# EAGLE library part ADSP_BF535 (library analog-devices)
Blackfin® Embedded Processor ADSP 535 Auto generated by make-symbol-device-package-bsdl.ulp Rev. 11 Source: ADSP_21535.bsdl http://www.analog.com/UploadedFiles/Data_Sheets/744511807ADSP_BF535_a.pdf
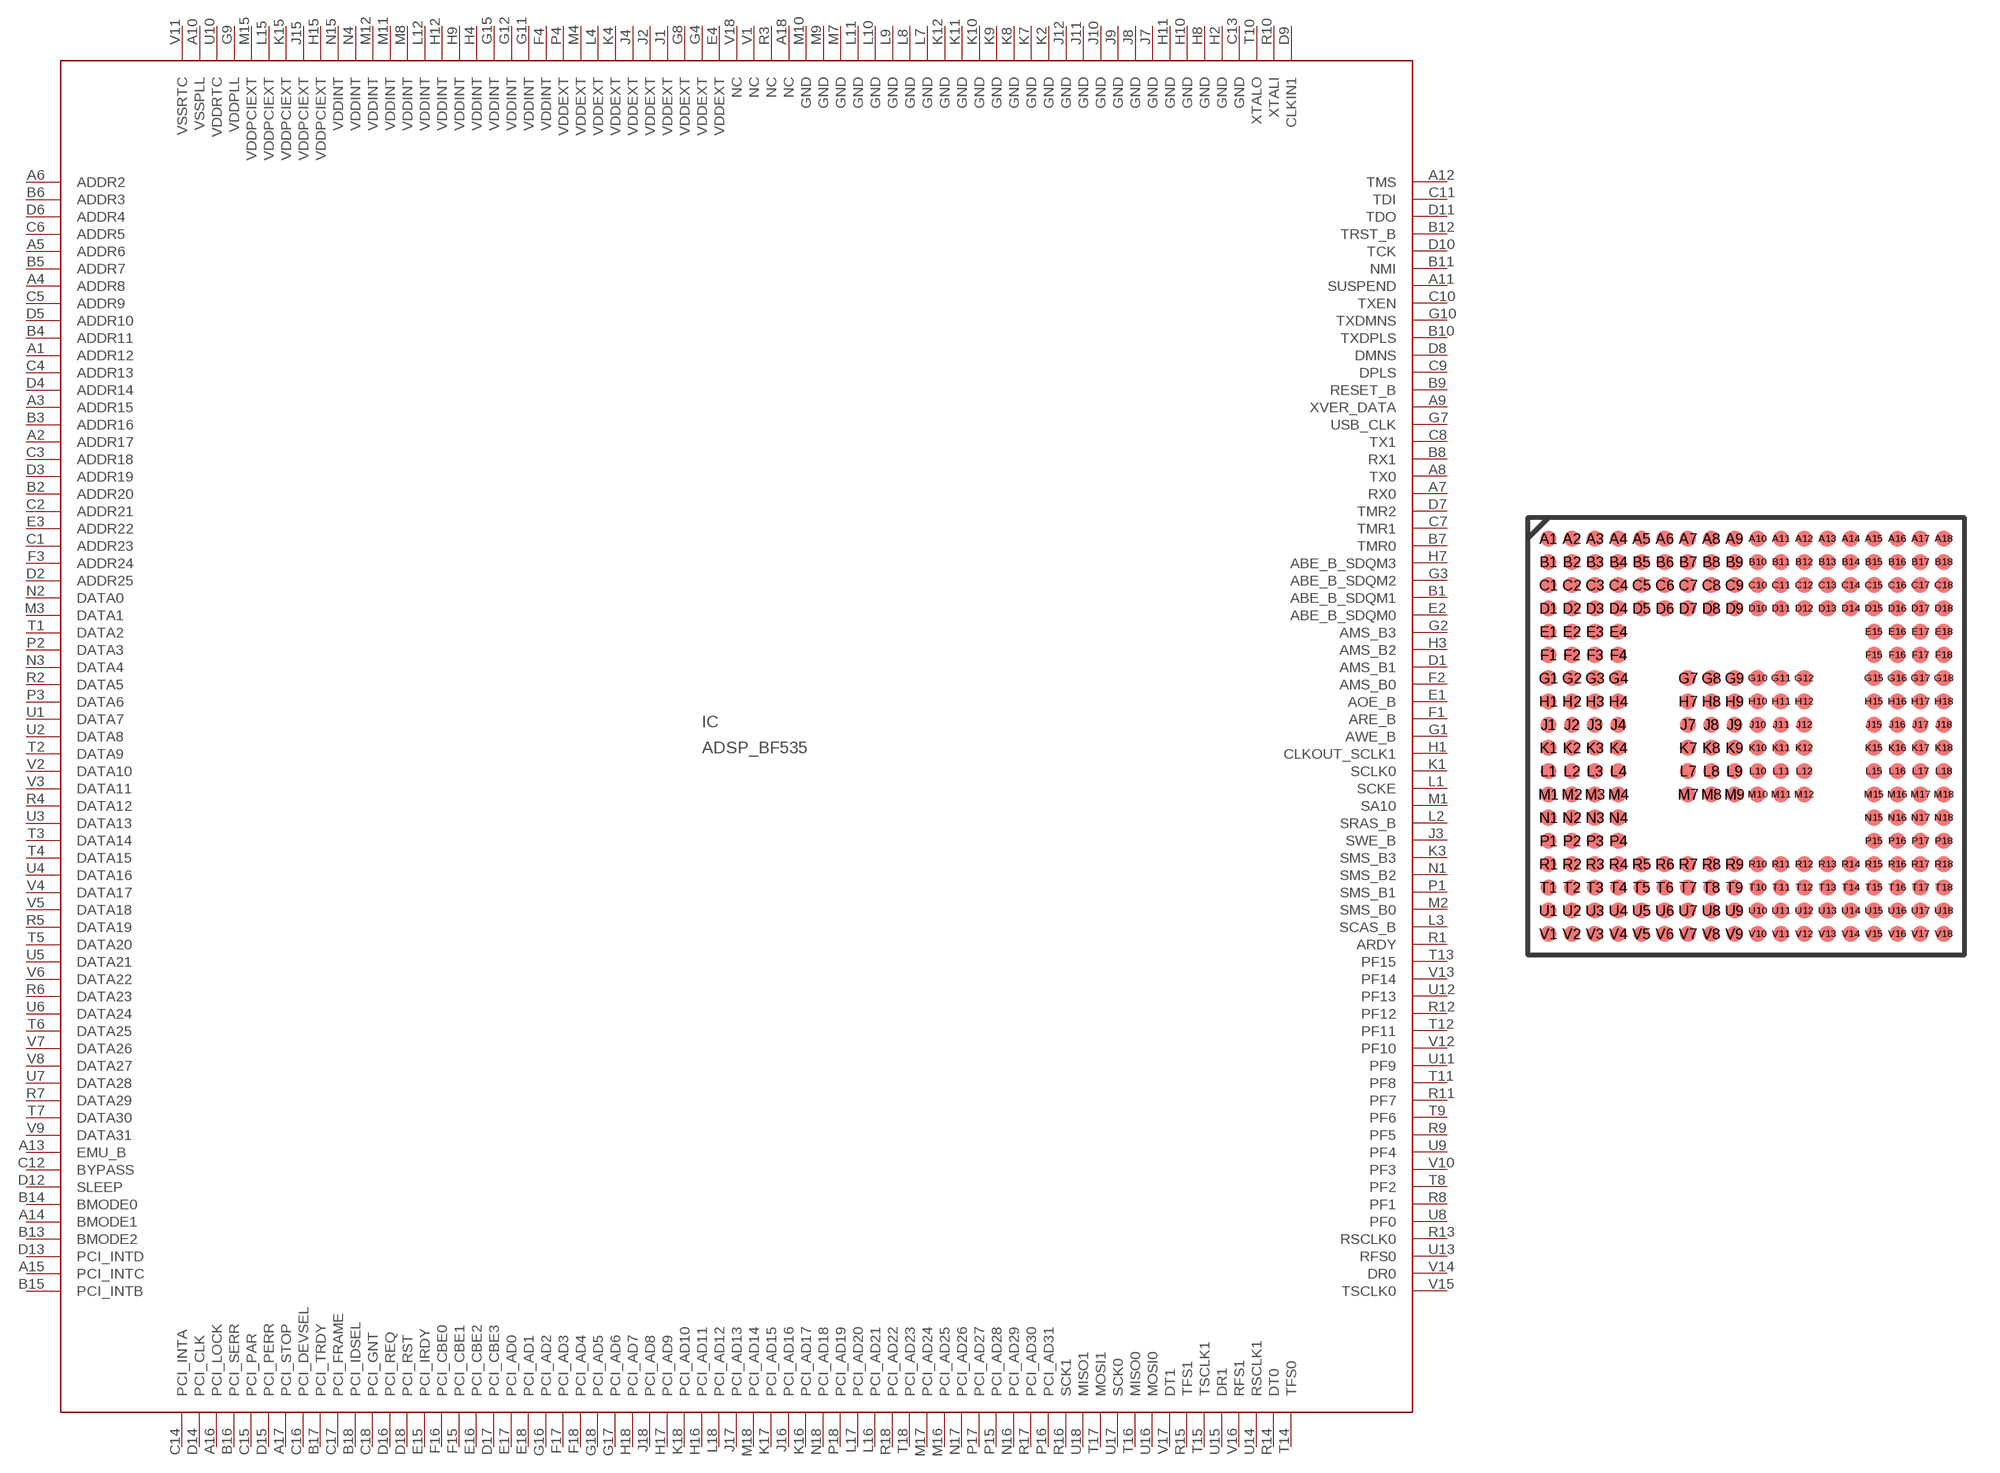
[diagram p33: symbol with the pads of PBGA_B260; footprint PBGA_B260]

Designator prefix IC

## ADSP_BF535 (OC_FARNELL: 1439074; OC_NEWARK: unknown)  [PBGA_B260]
A1  ADDR12  out
A2  ADDR17  out
A3  ADDR15  out
A4  ADDR8  out
A5  ADDR6  out
A6  ADDR2  out
A7  RX0  in
A8  TX0  out
A9  XVER_DATA  in
A10  VSSPLL  pwr
A11  SUSPEND  out
A12  TMS  in
A13  EMU_B  out
A14  BMODE1  in
A15  PCI_INTC  in
A16  PCI_LOCK  in
A17  PCI_STOP
A18  NC  pwr
B1  ABE_B_SDQM1  out
B2  ADDR20  out
B3  ADDR16  out
B4  ADDR11  out
B5  ADDR7  out
B6  ADDR3  out
B7  TMR0
B8  RX1  in
B9  RESET_B  in
B10  TXDPLS  out
B11  NMI  in
B12  TRST_B  in
B13  BMODE2  in
B14  BMODE0  in
B15  PCI_INTB  in
B16  PCI_SERR
B17  PCI_TRDY
B18  PCI_IDSEL  in
C1  ADDR23  out
C2  ADDR21  out
C3  ADDR18  out
C4  ADDR13  out
C5  ADDR9  out
C6  ADDR5  out
C7  TMR1
C8  TX1  out
C9  DPLS  in
C10  TXEN  out
C11  TDI  in
C12  BYPASS  in
C13  GND  pwr
C14  PCI_INTA
C15  PCI_PAR
C16  PCI_DEVSEL
C17  PCI_FRAME
C18  PCI_GNT  in
D1  AMS_B1  out
D2  ADDR25  out
D3  ADDR19  out
D4  ADDR14  out
D5  ADDR10  out
D6  ADDR4  out
D7  TMR2
D8  DMNS  in
D9  CLKIN1  pwr
D10  TCK  in
D11  TDO  out
D12  SLEEP  out
D13  PCI_INTD  in
D14  PCI_CLK  in
D15  PCI_PERR
D16  PCI_REQ  out
D17  PCI_CBE3
D18  PCI_RST
E1  AOE_B  out
E2  ABE_B_SDQM0  out
E3  ADDR22  out
E4  VDDEXT  pwr
E15  PCI_IRDY
E16  PCI_CBE2
E17  PCI_AD0
E18  PCI_AD1
F1  ARE_B  out
F2  AMS_B0  out
F3  ADDR24  out
F4  VDDINT  pwr
F15  PCI_CBE1
F16  PCI_CBE0
F17  PCI_AD3
F18  PCI_AD4
G1  AWE_B  out
G2  AMS_B3  out
G3  ABE_B_SDQM2  out
G4  VDDEXT  pwr
G7  USB_CLK  in
G8  VDDEXT  pwr
G9  VDDPLL  pwr
G10  TXDMNS  out
G11  VDDINT  pwr
G12  VDDINT  pwr
G15  VDDINT  pwr
G16  PCI_AD2
G17  PCI_AD6
G18  PCI_AD5
H1  CLKOUT_SCLK1  hiz
H2  GND  pwr
H3  AMS_B2  out
H4  VDDINT  pwr
H7  ABE_B_SDQM3  out
H8  GND  pwr
H9  VDDINT  pwr
H10  GND  pwr
H11  GND  pwr
H12  VDDINT  pwr
H15  VDDPCIEXT  pwr
H16  PCI_AD11
H17  PCI_AD9
H18  PCI_AD7
J1  VDDEXT  pwr
J2  VDDEXT  pwr
J3  SWE_B  out
J4  VDDEXT  pwr
J7  GND  pwr
J8  GND  pwr
J9  GND  pwr
J10  GND  pwr
J11  GND  pwr
J12  GND  pwr
J15  VDDPCIEXT  pwr
J16  PCI_AD16
J17  PCI_AD13
J18  PCI_AD8
K1  SCLK0  hiz
K2  GND  pwr
K3  SMS_B3  out
K4  VDDEXT  pwr
K7  GND  pwr
K8  GND  pwr
K9  GND  pwr
K10  GND  pwr
K11  GND  pwr
K12  GND  pwr
K15  VDDPCIEXT  pwr
K16  PCI_AD17
K17  PCI_AD15
K18  PCI_AD10
L1  SCKE  out
L2  SRAS_B  out
L3  SCAS_B  out
L4  VDDEXT  pwr
L7  GND  pwr
L8  GND  pwr
L9  GND  pwr
L10  GND  pwr
L11  GND  pwr
L12  VDDINT  pwr
L15  VDDPCIEXT  pwr
L16  PCI_AD21
L17  PCI_AD20
L18  PCI_AD12
M1  SA10  out
M2  SMS_B0  out
M3  DATA1
M4  VDDEXT  pwr
M7  GND  pwr
M8  VDDINT  pwr
M9  GND  pwr
M10  GND  pwr
M11  VDDINT  pwr
M12  VDDINT  pwr
M15  VDDPCIEXT  pwr
M16  PCI_AD25
M17  PCI_AD24
M18  PCI_AD14
N1  SMS_B2  out
N2  DATA0
N3  DATA4
N4  VDDINT  pwr
N15  VDDINT  pwr
N16  PCI_AD29
N17  PCI_AD26
N18  PCI_AD18
P1  SMS_B1  out
P2  DATA3
P3  DATA6
P4  VDDEXT  pwr
P15  PCI_AD28
P16  PCI_AD31
P17  PCI_AD27
P18  PCI_AD19
R1  ARDY  in
R2  DATA5
R3  NC  pwr
R4  DATA12
R5  DATA19
R6  DATA23
R7  DATA29
R8  PF1
R9  PF5
R10  XTALI  pwr
R11  PF7
R12  PF12
R13  RSCLK0
R14  DT0  out
R15  TFS1
R16  SCK1
R17  PCI_AD30
R18  PCI_AD22
T1  DATA2
T2  DATA9
T3  DATA14
T4  DATA15
T5  DATA20
T6  DATA25
T7  DATA30
T8  PF2
T9  PF6
T10  XTALO  pwr
T11  PF8
T12  PF11
T13  PF15
T14  TFS0
T15  TSCLK1
T16  MISO0
T17  MOSI1
T18  PCI_AD23
U1  DATA7
U2  DATA8
U3  DATA13
U4  DATA16
U5  DATA21
U6  DATA24
U7  DATA28
U8  PF0
U9  PF4
U10  VDDRTC  pwr
U11  PF9
U12  PF13
U13  RFS0
U14  RSCLK1
U15  DR1  in
U16  MOSI0
U17  SCK0
U18  MISO1
V1  NC  pwr
V2  DATA10
V3  DATA11
V4  DATA17
V5  DATA18
V6  DATA22
V7  DATA26
V8  DATA27
V9  DATA31
V10  PF3
V11  VSSRTC  pwr
V12  PF10
V13  PF14
V14  DR0  in
V15  TSCLK0
V16  RFS1
V17  DT1  out
V18  NC  pwr

## Footprint PBGA_B260 (pad centres in mm)
ADSP_21535.bsdl Auto generated by make-symbol-device-package-bsdl.ulp Rev. 11 Source: ADSP_21535.bsdl http://www.analog.com/UploadedFiles/Data_Sheets/744511807ADSP_BF535_a.pdf
smd 0.7 x 0.7: A1 -8.5,8.5; A2 -7.5,8.5; A3 -6.5,8.5; A4 -5.5,8.5; A5 -4.5,8.5; A6 -3.5,8.5; A7 -2.5,8.5; A8 -1.5,8.5; A9 -0.5,8.5; A10 0.5,8.5; A11 1.5,8.5; A12 2.5,8.5; A13 3.5,8.5; A14 4.5,8.5; A15 5.5,8.5; A16 6.5,8.5; A17 7.5,8.5; A18 8.5,8.5; B1 -8.5,7.5; B2 -7.5,7.5; B3 -6.5,7.5; B4 -5.5,7.5; B5 -4.5,7.5; B6 -3.5,7.5; B7 -2.5,7.5; B8 -1.5,7.5; B9 -0.5,7.5; B10 0.5,7.5; B11 1.5,7.5; B12 2.5,7.5; B13 3.5,7.5; B14 4.5,7.5; B15 5.5,7.5; B16 6.5,7.5; B17 7.5,7.5; B18 8.5,7.5; C1 -8.5,6.5; C2 -7.5,6.5; C3 -6.5,6.5; C4 -5.5,6.5; C5 -4.5,6.5; C6 -3.5,6.5; C7 -2.5,6.5; C8 -1.5,6.5; C9 -0.5,6.5; C10 0.5,6.5; C11 1.5,6.5; C12 2.5,6.5; C13 3.5,6.5; C14 4.5,6.5; C15 5.5,6.5; C16 6.5,6.5; C17 7.5,6.5; C18 8.5,6.5; D1 -8.5,5.5; D2 -7.5,5.5; D3 -6.5,5.5; D4 -5.5,5.5; D5 -4.5,5.5; D6 -3.5,5.5; D7 -2.5,5.5; D8 -1.5,5.5; D9 -0.5,5.5; D10 0.5,5.5; D11 1.5,5.5; D12 2.5,5.5; D13 3.5,5.5; D14 4.5,5.5; D15 5.5,5.5; D16 6.5,5.5; D17 7.5,5.5; D18 8.5,5.5; E1 -8.5,4.5; E2 -7.5,4.5; E3 -6.5,4.5; E4 -5.5,4.5; E15 5.5,4.5; E16 6.5,4.5; E17 7.5,4.5; E18 8.5,4.5; F1 -8.5,3.5; F2 -7.5,3.5; F3 -6.5,3.5; F4 -5.5,3.5; F15 5.5,3.5; F16 6.5,3.5; F17 7.5,3.5; F18 8.5,3.5; G1 -8.5,2.5; G2 -7.5,2.5; G3 -6.5,2.5; G4 -5.5,2.5; G7 -2.5,2.5; G8 -1.5,2.5; G9 -0.5,2.5; G10 0.5,2.5; G11 1.5,2.5; G12 2.5,2.5; G15 5.5,2.5; G16 6.5,2.5; G17 7.5,2.5; G18 8.5,2.5; H1 -8.5,1.5; H2 -7.5,1.5; H3 -6.5,1.5; H4 -5.5,1.5; H7 -2.5,1.5; H8 -1.5,1.5; H9 -0.5,1.5; H10 0.5,1.5; H11 1.5,1.5; H12 2.5,1.5; H15 5.5,1.5; H16 6.5,1.5; H17 7.5,1.5; H18 8.5,1.5; J1 -8.5,0.5; J2 -7.5,0.5; J3 -6.5,0.5; J4 -5.5,0.5; J7 -2.5,0.5; J8 -1.5,0.5; J9 -0.5,0.5; J10 0.5,0.5; J11 1.5,0.5; J12 2.5,0.5; J15 5.5,0.5; J16 6.5,0.5; J17 7.5,0.5; J18 8.5,0.5; K1 -8.5,-0.5; K2 -7.5,-0.5; K3 -6.5,-0.5; K4 -5.5,-0.5; K7 -2.5,-0.5; K8 -1.5,-0.5; K9 -0.5,-0.5; K10 0.5,-0.5; K11 1.5,-0.5; K12 2.5,-0.5; K15 5.5,-0.5; K16 6.5,-0.5; K17 7.5,-0.5; K18 8.5,-0.5; L1 -8.5,-1.5; L2 -7.5,-1.5; L3 -6.5,-1.5; L4 -5.5,-1.5; L7 -2.5,-1.5; L8 -1.5,-1.5; L9 -0.5,-1.5; L10 0.5,-1.5; L11 1.5,-1.5; L12 2.5,-1.5; L15 5.5,-1.5; L16 6.5,-1.5; L17 7.5,-1.5; L18 8.5,-1.5; M1 -8.5,-2.5; M2 -7.5,-2.5; M3 -6.5,-2.5; M4 -5.5,-2.5; M7 -2.5,-2.5; M8 -1.5,-2.5; M9 -0.5,-2.5; M10 0.5,-2.5; M11 1.5,-2.5; M12 2.5,-2.5; M15 5.5,-2.5; M16 6.5,-2.5; M17 7.5,-2.5; M18 8.5,-2.5; N1 -8.5,-3.5; N2 -7.5,-3.5; N3 -6.5,-3.5; N4 -5.5,-3.5; N15 5.5,-3.5; N16 6.5,-3.5; N17 7.5,-3.5; N18 8.5,-3.5; P1 -8.5,-4.5; P2 -7.5,-4.5; P3 -6.5,-4.5; P4 -5.5,-4.5; P15 5.5,-4.5; P16 6.5,-4.5; P17 7.5,-4.5; P18 8.5,-4.5; R1 -8.5,-5.5; R2 -7.5,-5.5; R3 -6.5,-5.5; R4 -5.5,-5.5; R5 -4.5,-5.5; R6 -3.5,-5.5; R7 -2.5,-5.5; R8 -1.5,-5.5; R9 -0.5,-5.5; R10 0.5,-5.5; R11 1.5,-5.5; R12 2.5,-5.5; R13 3.5,-5.5; R14 4.5,-5.5; R15 5.5,-5.5; R16 6.5,-5.5; R17 7.5,-5.5; R18 8.5,-5.5; T1 -8.5,-6.5; T2 -7.5,-6.5; T3 -6.5,-6.5; T4 -5.5,-6.5; T5 -4.5,-6.5; T6 -3.5,-6.5; T7 -2.5,-6.5; T8 -1.5,-6.5; T9 -0.5,-6.5; T10 0.5,-6.5; T11 1.5,-6.5; T12 2.5,-6.5; T13 3.5,-6.5; T14 4.5,-6.5; T15 5.5,-6.5; T16 6.5,-6.5; T17 7.5,-6.5; T18 8.5,-6.5; U1 -8.5,-7.5; U2 -7.5,-7.5; U3 -6.5,-7.5; U4 -5.5,-7.5; U5 -4.5,-7.5; U6 -3.5,-7.5; U7 -2.5,-7.5; U8 -1.5,-7.5; U9 -0.5,-7.5; U10 0.5,-7.5; U11 1.5,-7.5; U12 2.5,-7.5; U13 3.5,-7.5; U14 4.5,-7.5; U15 5.5,-7.5; U16 6.5,-7.5; U17 7.5,-7.5; U18 8.5,-7.5; V1 -8.5,-8.5; V2 -7.5,-8.5; V3 -6.5,-8.5; V4 -5.5,-8.5; V5 -4.5,-8.5; V6 -3.5,-8.5; V7 -2.5,-8.5; V8 -1.5,-8.5; V9 -0.5,-8.5; V10 0.5,-8.5; V11 1.5,-8.5; V12 2.5,-8.5; V13 3.5,-8.5; V14 4.5,-8.5; V15 5.5,-8.5; V16 6.5,-8.5; V17 7.5,-8.5; V18 8.5,-8.5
